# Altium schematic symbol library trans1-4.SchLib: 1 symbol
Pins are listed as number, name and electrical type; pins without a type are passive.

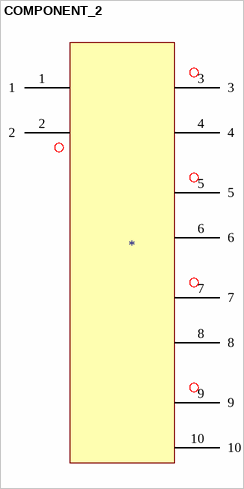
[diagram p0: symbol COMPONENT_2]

## COMPONENT_2
designator *
pins: 1, 2, 3, 4, 5, 6, 7, 8, 9, 10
